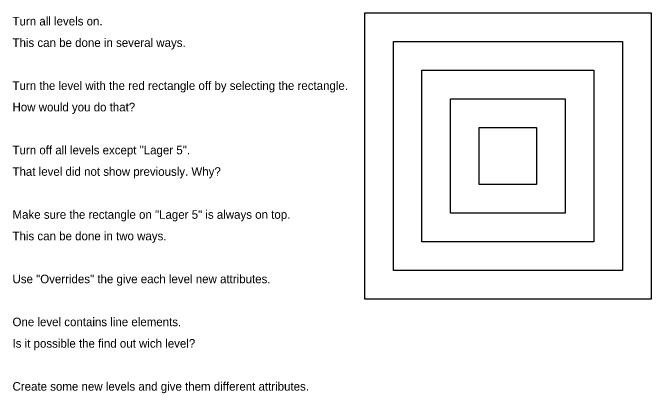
# Model space of a CAD drawing. Extents: x 1517688.1 to 1517710.4, y 6495351.2 to 6495364.5.
import ezdxf

# ---------------------------------------------------------------- set-up
doc = ezdxf.new("R2010")
doc.units = 0
for name, color, linetype in [('Instruktioner', 7, 'Continuous'), ('Lager 1', 7, 'Continuous'), ('Lager 2', 7, 'Continuous'), ('Lager 3', 7, 'Continuous'), ('Lager 4', 7, 'Continuous'), ('Lager 5', 7, 'Continuous')]:
    doc.layers.add(name, color=color, linetype=linetype)

msp = doc.modelspace()

# ---------------------------------------------------------------- linework, layer by layer
at = {"layer": 'Lager 1'}
msp.add_lwpolyline([(1517700.355, 6495364.497), (1517710.355, 6495364.497), (1517710.355, 6495354.497), (1517700.355, 6495354.497)], close=True, dxfattribs=at)
at = {"layer": 'Lager 2'}
for p, q in [((1517701.355, 6495355.497), (1517701.355, 6495363.497)), ((1517701.355, 6495363.497), (1517709.355, 6495363.497)), ((1517709.355, 6495363.497), (1517709.355, 6495355.497)), ((1517709.355, 6495355.497), (1517701.355, 6495355.497))]:
    msp.add_line(p, q, dxfattribs=at)
msp.add_lwpolyline([(1517701.355, 6495363.497), (1517709.355, 6495363.497), (1517709.355, 6495355.497), (1517701.355, 6495355.497)], close=True, dxfattribs=at)
at = {"layer": 'Lager 3'}
msp.add_lwpolyline([(1517702.355, 6495362.497), (1517708.355, 6495362.497), (1517708.355, 6495356.497), (1517702.355, 6495356.497)], close=True, dxfattribs=at)
at = {"layer": 'Lager 4'}
msp.add_lwpolyline([(1517703.355, 6495361.497), (1517707.355, 6495361.497), (1517707.355, 6495357.497), (1517703.355, 6495357.497)], close=True, dxfattribs=at)
at = {"layer": 'Lager 5'}
msp.add_lwpolyline([(1517704.355, 6495360.497), (1517706.355, 6495360.497), (1517706.355, 6495358.497), (1517704.355, 6495358.497)], close=True, dxfattribs=at)

# ---------------------------------------------------------------- texts
at = {"layer": 'Instruktioner'}
for s, p in [('Turn all levels on.', (1517688.065, 6495364.054)), ('This can be done in several ways.', (1517688.065, 6495363.304)), ('Turn the level with the red rectangle off by selecting the rectangle.', (1517688.065, 6495361.804)), ('How would you do that?', (1517688.065, 6495361.054)), ('Turn off all levels except "Lager 5".', (1517688.065, 6495359.554)), ('That level did not show previously. Why?', (1517688.065, 6495358.804)), ('Make sure the rectangle on "Lager 5" is always on top.', (1517688.065, 6495357.304)), ('This can be done in two ways.', (1517688.065, 6495356.554)), ('Use "Overrides" the give each level new attributes.', (1517688.065, 6495355.054)), ('One level contains line elements.', (1517688.065, 6495353.554)), ('Is it possible the find out wich level?', (1517688.065, 6495352.804)), ('Create some new levels and give them different attributes.', (1517688.065, 6495351.304))]:
    msp.add_text(s, height=0.3, dxfattribs=at).set_placement(p)

doc.saveas('drawing.dxf')
